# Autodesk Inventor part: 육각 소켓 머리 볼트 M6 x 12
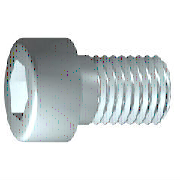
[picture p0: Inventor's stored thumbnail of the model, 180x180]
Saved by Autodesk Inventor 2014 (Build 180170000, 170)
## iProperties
IsCustomPart: 1
Created: 2012-02
Part Number: 육각 소켓 머리 볼트 M6 x 12
Material: 스테인리스강
Description: 6각 소켓 머리 캡 나사
Document SubType Name: Modeling
Standard: ISO 4762
Designer: mdu-01
Standard Revision: Fourth edition 2004-03-01
Standards Organization: ISO
Language: ko-KR
Size Designation: M6 x 12
Categories: <MemberInstance><Categories><Category DisplayName="조임쇠" InternalName="e4da775c-781d-43d5-af7c-5136215cf5a6" Mnemonic="FSTN"><Category DisplayName="볼트" InternalN
Density: 7.75 g/cm^3
Mass: 5.625 g
Surface Area: 6.13303 cm^2
Volume: 0.725807 cm^3
Appearance: 반광택
Author: mdu-01
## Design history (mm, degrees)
sketch "스케치1"
  geometry: L1 (-1.333, 0)-(12, 0); L2 (12, 0)-(12, 3); L3 (12, 3)-(2.5, 3); L4 (2.5, 3)-(1.886, 3); L5 (1.886, 3)-(0, 3); L6 (0, 3)-(0, 5); L7 (0, 5)-(-6, 5); L8 (-6, 5)-(-6, 2.887); L9 (-6, 2.887)-(-3, 2.887); L10 (-3, 2.887)-(-1.333, 0); L11 (-9.6, 0)-(15.6, 0) reference; L12 (0, -1)-(0, 6) reference; L13 (2.5, 3)-(0, 3)
  constraints: 22 end point, 6 parallel, 2 collinear, 2 perpendicular, 1 horizontal, 1 point on line
  dimensions: "d1" = 9.5 distance from line of L3.end L2 (= GEL); "d2" = 0.61355 distance of L4.end L3.end (computed from GAL); "d3" = 6 distance between parallel lines of L8 L6 (= KOH); "d4" = 3 distance of L8.end L9.end (= INTI); "d5" = 60 deg angle of L10 L1; "d6" = 6 diameter of L3 L1 (= GD); "d7" = 6 diameter of L5 L1 (= BDM); "d8" = 5.7735 diameter of L9 L1 (= 1.1547 x SW); "d9" = 10 diameter of L7 L1 (= KOD); "d26" = 12 distance between parallel lines of L12 L2 (= NLG)
revolve "본체" sketch "스케치1" stored, may be unused: angle "d10" = 90 deg
sketch "스케치2"
  geometry: L1 (0, -7)-(0, 7) reference; L2 (-7, 0)-(7, 0) reference; L3 (2.887, 0)-(1.443, -2.5); L4 (1.443, -2.5)-(-1.443, -2.5); L5 (-1.443, -2.5)-(-2.887, 0); L6 (-2.887, 0)-(-1.443, 2.5); L7 (-1.443, 2.5)-(1.443, 2.5); L8 (1.443, 2.5)-(2.887, 0); 2 further points
  constraints: 12 end point, 1 coincident, 1 horizontal alignment, 1 point on line, 12 other
extrude "슬롯" join sketch "스케치2" stored distance "d11" = 10; taper "d12" = 0 deg
workplane "Work Plane1"
fillet "Fillet2" dims "d30" = 0.05 (= R)
body "Solid1"
fillet "모깎기1" dims "d17" = 0.6 (= RR)
feature "스레드" dims "d13" = 9.5 (= GEL), "d14" = 0
chamfer "모따기1" distance "d15" = 0.61345 (= -0.5 x SPD + 0.5 x GD); stored, may be unused: second distance "d16" = 0.61345 (= GUL), angle "d27" = 45 deg
other parameters: "GD" = 6 [user parameter; used in 2 equation terms], "NLG" = 12 [user parameter; used in 1 equation term], "GEL" = 9.5 [user parameter; used in 2 equation terms], "KOD" = 10 [user parameter; used in 1 equation term], "KOH" = 6 [user parameter; used in 1 equation term], "INTI" = 3 [user parameter; used in 1 equation term], "GAL" = 0.61345 (= 0.61345 x PTC) [user parameter; used in 1 equation term], "GUL" = 0.61345 (= 0.61345 x PTC) [user parameter; used in 1 equation term], "BDM" = 6 (= NND) [user parameter; used in 1 equation term], "SW" = 5 [user parameter; used in 2 equation terms], "RR" = 0.6 [user parameter; used in 1 equation term], "SPD" = 4.7731 (= NND - 1.2269 x PTC) [user parameter; used in 1 equation term], "d19" = 0, "d28" = 0, "d29" = 0, "R" = 0.05 [user parameter; used in 1 equation term], "TOA" = 30 deg [user parameter], "GD1" = 4.7731 (= THREADDIA - 1.2269 x PTC) [user parameter], "THREADDIA" = 6 [user parameter; used in 1 equation term], "FAWI" = 45 deg [user parameter], "PTC" = 1 [user parameter; used in 5 equation terms], "NND" = 6 [user parameter; used in 2 equation terms], "E0" = 5.775 (= 1.155 x SW) [user parameter]
